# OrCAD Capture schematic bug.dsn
size A; title: Bug; rev: 0; company: Company Name; note: xxxxx; note: Street Address; note: City, Province, Postal Code
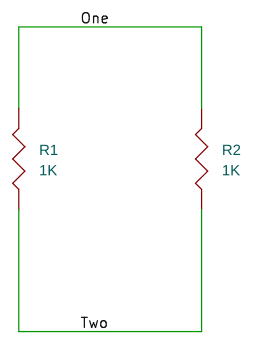
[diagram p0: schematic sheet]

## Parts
R1  1K  [resc1608x55n]
R2  1K  [resc1608x55n]

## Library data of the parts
R1 R2 = RESISTOR_5: Resistor, chip; Case Size: 0603; Manufacturer: Generic; Op Temp Range: -40C/+85C; Part Number: Generic; Substitutable: Yes; TH/SMT: SMT; Tol: 5%; Wattage: 0.1W

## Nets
One: R1.1 R2.1
Two: R1.2 R2.2
